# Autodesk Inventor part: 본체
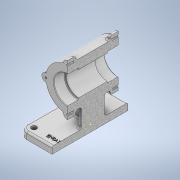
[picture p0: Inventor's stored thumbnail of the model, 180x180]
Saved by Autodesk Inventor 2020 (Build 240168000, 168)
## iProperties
Created: 2022-11
Part Number: 본체
Material: 일반
Document SubType Name: Modeling
Designer: owner
Density: 1 g/cm^3
Appearance: 기본값
Mass: 450.025 g
Surface Area: 797.07 cm^2
Volume: 450.025 cm^3
Author: owner
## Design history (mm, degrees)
sketch "스케치1"
  geometry: L1 (55, -65)-(-55, -65); L2 (-55, -65)-(-55, 65); L3 (-55, 65)-(55, 65); L4 (55, 65)-(55, -65); L5 (55, -65)-(-55, 65); L6 (-55, -65)-(55, 65); 1 further point
  constraints: 12 end point, 2 midpoint, 2 parallel, 1 horizontal, 1 perpendicular
  dimensions: "d0" = 110 distance of L2.end L3.end; "d1" = 130 distance of L1.end L2.end
extrude "돌출1" new body sketch "스케치1" distance "d2" = 12; taper "d3" = 0 deg
node "작업 평면2"
sketch "스케치3"
  geometry: L1 (0, 0)-(110, 0) reference; C1 r 37 at (55, 82); 2 further points
  constraints: 1 centre point, 1 midpoint, 1 vertical alignment
  dimensions: "d8" = 74 diameter of C1; "d9" = 82 distance from line of L1 C1.centre
extrude "돌출2" join sketch "스케치3" stored distance "d10" = 87; taper "d11" = 0 deg
sketch "스케치4"
  geometry: C1 r 37 at (0, 0) reference; C2 r 21 at (0, 0); 1 further point
  constraints: 1 centre point, 1 coincident
  dimensions: "d12" = 42 diameter of C2
extrude "돌출3" cut sketch "스케치4" extent not by distance; stored distance "d13" = 0; taper "d14" = 0 deg
sketch "스케치5"
  geometry: C1 r 21 at (0, 0) reference; C2 r 23.5 at (0, 0); 1 further point
  constraints: 1 centre point, 1 coincident
  dimensions: "d15" = 47 diameter of C2
extrude "돌출4" cut sketch "스케치5" distance "d16" = 19; taper "d17" = 0 deg
sketch "스케치6"
  geometry: A1 r 37 centre (0, 0) between (0, 37) and (-6.969, 36.338) reference; A2 r 7 centre (0, 37) between (6.969, 36.338) and (-6.969, 36.338); 1 further point
  constraints: 5 point on circle, 1 centre point, 1 vertical alignment
  dimensions: "d18" = 14 diameter of A2
extrude "돌출5" join sketch "스케치6" distance "d19" = 14; taper "d20" = 0 deg
fillet "모깎기1" dims "d21" = 3
sketch "스케치7"
  geometry: A1 r 7 centre (55, 119) between (61.969, 118.338) and (48.031, 118.338) reference; 4 further points
  constraints: 1 coincident
hole "구멍1" sketch "스케치7" at (55, 119) diameter "d22" = 3.242; stored, may be unused: countersink angle "d26" = 90 deg, drill point angle "d28" = 118 deg; dims "d23" = 8, "d24" = 4, "d25" = 2, "d27" = 10
fillet "모깎기3" dims "d33" = 3
sketch "스케치10"
  geometry: L1 (29.664, 55.036)-(14, 12); L2 (0, 12)-(110, 12) reference; L3 (0, 0)-(0, 12) reference; L4 (80.336, 55.036)-(96, 12); L5 (110, 0)-(110, 12) reference; A1 r 37 centre (55, 82) between (19.137, 72.896) and (45.896, 46.138) reference; A2 r 37 centre (55, 82) between (64.104, 46.138) and (90.862, 72.896) reference; A3 r 37 centre (55, 82) between (90.862, 91.104) and (64.104, 117.863) reference; A4 r 37 centre (55, 82) between (57.543, 118.913) and (52.457, 118.913) reference; A5 r 37 centre (55, 82) between (45.896, 117.863) and (19.137, 91.104) reference; A6 r 37 centre (55, 82) between (18.087, 84.543) and (18.087, 79.457) reference; A7 r 37 centre (55, 82) between (19.137, 72.896) and (45.896, 46.138) reference; A8 r 37 centre (55, 82) between (52.457, 45.087) and (57.543, 45.088) reference; A9 r 37 centre (55, 82) between (64.104, 46.138) and (90.862, 72.896) reference; A10 r 37 centre (55, 82) between (91.912, 79.457) and (91.912, 84.543) reference; A11 r 37 centre (55, 82) between (64.104, 46.138) and (90.862, 72.896) reference; A12 r 37 centre (55, 82) between (52.457, 45.088) and (57.543, 45.088) reference; A13 r 37 centre (55, 82) between (19.137, 72.896) and (45.896, 46.138) reference; A14 r 37 centre (55, 82) between (18.087, 84.543) and (18.087, 79.457) reference; A15 r 37 centre (55, 82) between (45.896, 117.863) and (19.137, 91.104) reference; A16 r 37 centre (55, 82) between (57.543, 118.913) and (52.457, 118.913) reference; A17 r 37 centre (55, 82) between (90.862, 91.104) and (64.104, 117.863) reference; A18 r 37 centre (55, 82) between (91.912, 79.457) and (91.912, 84.543) reference; 19 further points
  constraints: 4 end point, 2 point on circle, 2 point on line, 16 other
  dimensions: "d42" = 110 deg angle of L2 L1; "d43" = 14 distance from line of L3 L1.end; "d44" = 110 deg angle of L2 L4; "d45" = 14 distance from line of L5 L4.end
extrude "돌출7" join sketch "스케치10" stored distance "d46" = 10; taper "d47" = 0 deg
sketch "스케치13"
  geometry: L1 (12, 15)-(31.944, 15); L2 (-25.2, -5)-(151.2, -5) reference; 1 further point
  constraints: 2 end point
  dimensions: "d58" = 20 distance between parallel lines of L2 L1
feature "리브1" sketch "스케치13" dims "d59" = 1, "d60" = 10, "d61" = 0, "d62" = 0, "d63" = 1, "d64" = 1
fillet "모깎기6" dims "d65" = 3
fillet "모깎기7" dims "d66" = 3
fillet "모깎기8" dims "d67" = 3
fillet "모깎기9" dims "d68" = 3
fillet "모깎기10" dims "d69" = 3
sketch "스케치14"
  geometry: 1 further point
sketch "스케치15"
  geometry: L1 (0, 91)-(0, -91) reference; L2 (77, 5)-(-77, 5) reference; 2 further points
  constraints: 1 vertical alignment, 1 other
  dimensions: "d70" = 58 distance from line of point (0, -53) L2
feature "엠보싱1" sketch "스케치15" dims "d0" = 110, "d1" = 130, "d71" = 0.5, "d72" = 0
fillet "모깎기11" dims "d73" = 12
fillet "모깎기12" dims "d74" = 3
sketch "스케치17"
  geometry: A1 r 9 centre (43, -53) between (43, -62) and (52, -53) reference; 2 further points
  constraints: 1 coincident
hole "구멍2" sketch "스케치17" at (43, -53) diameter "d76" = 9; stored, may be unused: countersink angle "d80" = 90 deg, drill point angle "d82" = 0 deg; dims "d77" = 8, "d78" = 4, "d79" = 2, "d81" = 10
chamfer "모따기1" distance "d83" = 1; stored, may be unused: second distance "d84" = 2, angle "d85" = 45 deg
fillet "모깎기14" dims "d87" = 1
node "솔리드1"
mirror "미러1"
pattern_circular "원형 패턴2" dims "d35" = 360 deg
mirror "미러3"
mirror "미러5"
mirror "미러6"
mirror "미러7"
node "투영된 루프2"
feature "A9D066F2-1C7D-4E18-AEED-F7BC21143FA4" dims "d76" = 9, "d77" = 8, "d78" = 4, "d79" = 2, "d80" = 90 deg, "d81" = 10, "d82" = 0
